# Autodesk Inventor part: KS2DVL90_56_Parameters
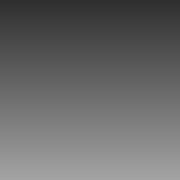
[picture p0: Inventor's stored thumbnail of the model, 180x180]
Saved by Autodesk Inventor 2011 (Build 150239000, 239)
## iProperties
Created: 2010-11
Document SubType Name: Modeling
Designer: TB
Density: 1 g/cm^3
Slaglengde: 100,000 mm
Vinkel_Minusport: 0.00 deg
Forlengelse_rør: 0.000 mm
Minusport2: 180.00 deg
Author: TB
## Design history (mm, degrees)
other parameters: "Slaglengde" = 100 [user parameter], "Forlengelse_rør" = 0 [user parameter], "Vinkel_Minusport" = 0 deg [user parameter], "Minusport2" = 180 deg [user parameter]
